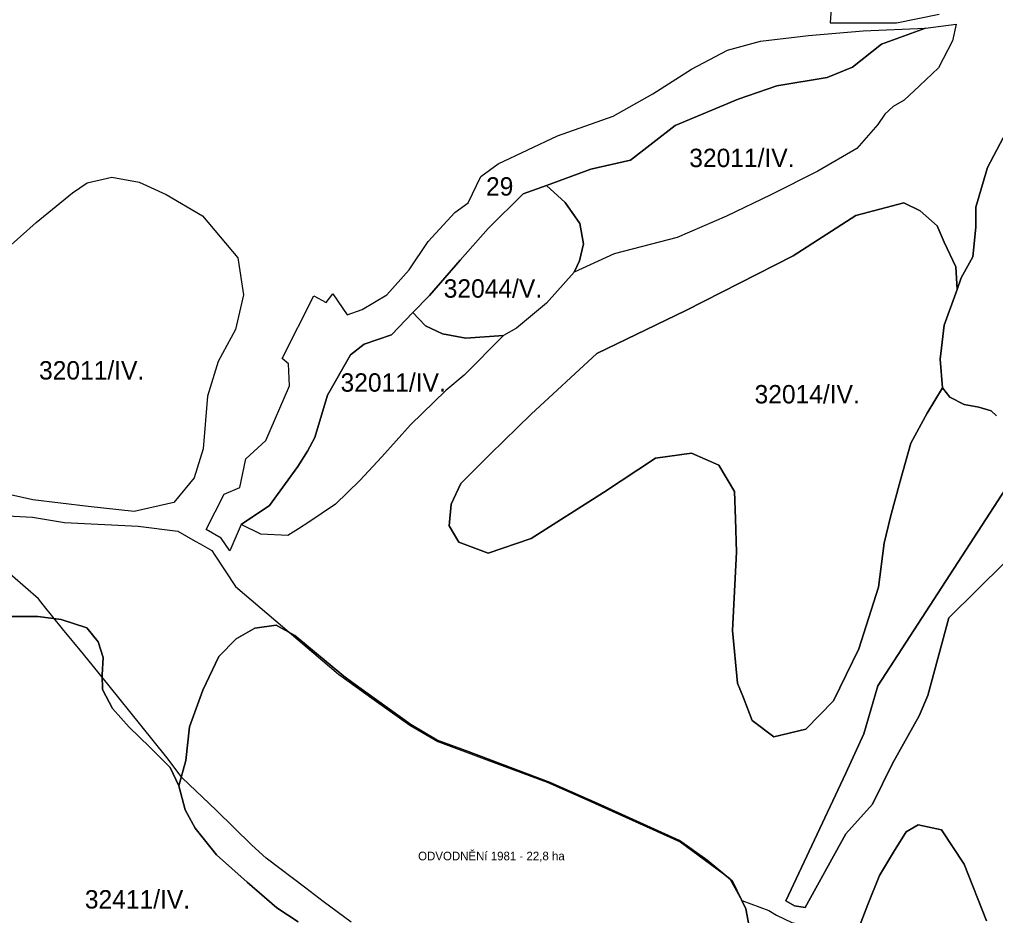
# Model space of a CAD drawing. Extents: x -521621 to -516761, y -1190184 to -1184927.
# Drawn here: x -518211 to -517414, y -1187665 to -1186934 of the extents above; entities that cross this region are included whole.
import ezdxf

# ---------------------------------------------------------------- set-up
doc = ezdxf.new("R2010")
doc.units = 0
doc.layers.add('BPEJ_s', color=7, linetype='Continuous')
doc.layers.add('odvodneni_s', color=7, linetype='Continuous')

msp = doc.modelspace()

# ---------------------------------------------------------------- linework, layer by layer
at = {"layer": 'BPEJ_s'}
for points in [[(-518029.72, -1187346.19), (-518038.98, -1187367.79), (-518045.96, -1187357.39), (-518058.12, -1187350.38), (-518043.45, -1187321.5), (-518030.79, -1187315.94), (-518025.93, -1187292.6), (-518009.65, -1187277.77), (-517990.31, -1187233), (-517991.03, -1187215.19), (-517996.11, -1187210.68), (-517970.35, -1187159.68), (-517960.2, -1187165.13), (-517954.93, -1187157.98), (-517943.27, -1187175.11), (-517931.05, -1187170.78), (-517910.74, -1187158.92), (-517892.69, -1187138.41), (-517877.03, -1187115.33), (-517855.2, -1187091.6), (-517844.41, -1187083.69), (-517834, -1187062.21), (-517819.95, -1187051.92), (-517771.39, -1187028.94), (-517726.14, -1187013.04), (-517693.57, -1186994.78), (-517662.24, -1186974.5), (-517632.81, -1186959.09), (-517605.84, -1186951.66), (-517566.49, -1186946.97), (-517521.9, -1186943.39), (-517470.99, -1186941.19), (-517445.99, -1186937.81), (-517449.03, -1186951.31), (-517460.58, -1186973.53), (-517476.03, -1186988.1), (-517488.46, -1186999.83), (-517497.52, -1187004.99), (-517504.38, -1187011.23), (-517509.98, -1187019.85), (-517527.2, -1187039.23), (-517559.06, -1187057.76), (-517597.31, -1187077.14), (-517633.59, -1187094.62), (-517673.9, -1187112.1), (-517725.3, -1187125.21), (-517757.89, -1187140.33), (-517780.4, -1187165.55), (-517804.92, -1187186.05), (-517815.67, -1187192.1), (-517847.58, -1187224.37), (-517862.7, -1187236.81), (-517891.59, -1187265.04), (-517914.77, -1187290.93), (-517932.91, -1187310.42), (-517952.73, -1187329.58), (-517974.57, -1187344.37), (-517982.97, -1187349.75), (-517991.7, -1187355.13), (-518013.54, -1187354.12)], [(-518029.72, -1187346.19), (-518038.98, -1187367.79), (-518045.96, -1187357.39), (-518058.12, -1187350.38), (-518043.45, -1187321.5), (-518030.79, -1187315.94), (-518025.93, -1187292.6), (-518009.65, -1187277.77), (-517990.31, -1187233), (-517991.03, -1187215.19), (-517996.11, -1187210.68), (-517970.35, -1187159.68), (-517960.2, -1187165.13), (-517954.93, -1187157.98), (-517943.27, -1187175.11), (-517931.05, -1187170.78), (-517910.74, -1187158.92), (-517892.69, -1187138.41), (-517877.03, -1187115.33), (-517855.2, -1187091.6), (-517844.41, -1187083.69), (-517834, -1187062.21), (-517819.95, -1187051.92), (-517771.39, -1187028.94), (-517726.14, -1187013.04), (-517693.57, -1186994.78), (-517662.24, -1186974.5), (-517632.81, -1186959.09), (-517605.84, -1186951.66), (-517566.49, -1186946.97), (-517521.9, -1186943.39), (-517470.99, -1186941.19), (-517507.04, -1186954.14), (-517530.71, -1186972.87), (-517551.35, -1186981.41), (-517592.36, -1186988.3), (-517624, -1186999.04), (-517675.47, -1187020.56), (-517711.98, -1187048.8), (-517744.18, -1187056.27), (-517780.4, -1187069.41), (-517799.61, -1187076.37), (-517828.16, -1187104.61), (-517851.06, -1187130.52), (-517875.94, -1187159.33), (-517889.51, -1187173.34), (-517906.94, -1187191.35), (-517929.34, -1187198.96), (-517940.34, -1187207.76), (-517959.14, -1187240.79), (-517969.54, -1187275.21), (-517975.54, -1187286.42), (-517983.54, -1187298.83), (-517995.59, -1187315.89), (-518006.5, -1187330.73)], [(-517780.4, -1187069.41), (-517744.18, -1187056.27), (-517711.98, -1187048.8), (-517675.47, -1187020.56), (-517624, -1186999.04), (-517592.36, -1186988.3), (-517551.35, -1186981.41), (-517530.71, -1186972.87), (-517507.04, -1186954.14), (-517470.99, -1186941.19), (-517445.99, -1186937.81), (-517449.03, -1186951.31), (-517460.58, -1186973.53), (-517476.03, -1186988.1), (-517488.46, -1186999.83), (-517497.52, -1187004.99), (-517504.38, -1187011.23), (-517509.98, -1187019.85), (-517527.2, -1187039.23), (-517559.06, -1187057.76), (-517597.31, -1187077.14), (-517633.59, -1187094.62), (-517673.9, -1187112.1), (-517725.3, -1187125.21), (-517757.89, -1187140.33), (-517753.52, -1187130.92), (-517750.16, -1187117.14), (-517753.18, -1187100.67), (-517765.28, -1187083.53)], [(-517889.51, -1187173.34), (-517875.94, -1187159.33), (-517851.06, -1187130.52), (-517828.16, -1187104.61), (-517799.61, -1187076.37), (-517780.4, -1187069.41), (-517765.28, -1187083.53), (-517753.18, -1187100.67), (-517750.16, -1187117.14), (-517753.52, -1187130.92), (-517757.89, -1187140.33), (-517780.4, -1187165.55), (-517804.92, -1187186.05), (-517815.67, -1187192.1), (-517846.24, -1187194.12), (-517865.39, -1187190.76), (-517879.16, -1187184.03), (-517884.54, -1187178.32)], [(-517457.21, -1187234.78), (-517469.69, -1187255.33), (-517483.07, -1187279.92), (-517491.81, -1187310.79), (-517499.72, -1187340.02), (-517504.83, -1187361.61), (-517509.62, -1187397.54), (-517525.58, -1187447.85), (-517546.33, -1187490.17), (-517568.67, -1187513.33), (-517595.01, -1187519.72), (-517612.56, -1187506.14), (-517619.74, -1187487.78), (-517624.53, -1187475.8), (-517628.52, -1187432.68), (-517625.33, -1187368.8), (-517626.13, -1187341.65), (-517626.93, -1187319.29), (-517639.7, -1187297.73), (-517662.04, -1187288.14), (-517691.57, -1187292.14), (-517733.86, -1187320.08), (-517792.92, -1187357.61), (-517828.03, -1187369.59), (-517851.97, -1187360.81), (-517859.95, -1187347.23), (-517858.36, -1187329.67), (-517850.38, -1187312.9), (-517826.44, -1187288.94), (-517792.92, -1187256.2), (-517739.45, -1187206.69), (-517666.83, -1187171.56), (-517579.04, -1187126.84), (-517527.97, -1187094.1), (-517488.87, -1187083.72), (-517475.57, -1187090.31), (-517461.64, -1187102.35), (-517455.94, -1187115.66), (-517446.44, -1187135.94), (-517445.18, -1187154.31), (-517455.94, -1187183.46), (-517459.11, -1187211.34)], [(-518029.72, -1187346.19), (-518006.5, -1187330.73), (-517995.59, -1187315.89), (-517983.54, -1187298.83), (-517975.54, -1187286.42), (-517969.54, -1187275.21), (-517959.14, -1187240.79), (-517940.34, -1187207.76), (-517929.34, -1187198.96), (-517906.94, -1187191.35), (-517889.51, -1187173.34), (-517884.54, -1187178.32), (-517879.16, -1187184.03), (-517865.39, -1187190.76), (-517846.24, -1187194.12), (-517815.67, -1187192.1), (-517847.58, -1187224.37), (-517862.7, -1187236.81), (-517891.59, -1187265.04), (-517914.77, -1187290.93), (-517932.91, -1187310.42), (-517952.73, -1187329.58), (-517974.57, -1187344.37), (-517982.97, -1187349.75), (-517991.7, -1187355.13), (-518013.54, -1187354.12)]]:
    msp.add_lwpolyline(points, close=True, dxfattribs=at)
for points in [[(-517407.81, -1187030.75), (-517420.48, -1187054.83), (-517429.98, -1187087.15), (-517429.98, -1187103.62), (-517432.51, -1187127.7), (-517442.01, -1187144.81), (-517445.18, -1187154.31), (-517446.44, -1187135.94), (-517455.94, -1187115.66), (-517461.64, -1187102.35), (-517475.57, -1187090.31), (-517488.87, -1187083.72), (-517527.97, -1187094.1), (-517579.04, -1187126.84), (-517666.83, -1187171.56), (-517739.45, -1187206.69), (-517792.92, -1187256.2), (-517826.44, -1187288.94), (-517850.38, -1187312.9), (-517858.36, -1187329.67), (-517859.95, -1187347.23), (-517851.97, -1187360.81), (-517828.03, -1187369.59), (-517792.92, -1187357.61), (-517733.86, -1187320.08), (-517691.57, -1187292.14), (-517662.04, -1187288.14), (-517639.7, -1187297.73), (-517626.93, -1187319.29), (-517626.13, -1187341.65), (-517625.33, -1187368.8), (-517628.52, -1187432.68), (-517624.53, -1187475.8), (-517619.74, -1187487.78), (-517612.56, -1187506.14), (-517595.01, -1187519.72), (-517568.67, -1187513.33), (-517546.33, -1187490.17), (-517525.58, -1187447.85), (-517509.62, -1187397.54), (-517504.83, -1187361.61), (-517499.72, -1187340.02), (-517491.81, -1187310.79), (-517483.07, -1187279.92), (-517469.69, -1187255.33), (-517457.21, -1187234.78), (-517451.13, -1187242.22), (-517439.66, -1187248.23), (-517427.65, -1187250.41), (-517417.55, -1187253.42), (-517413.18, -1187257.52)], [(-517413.18, -1187257.52), (-517417.55, -1187253.42), (-517427.65, -1187250.41), (-517439.66, -1187248.23), (-517451.13, -1187242.22), (-517457.21, -1187234.78), (-517459.11, -1187211.34), (-517455.94, -1187183.46), (-517445.18, -1187154.31), (-517442.01, -1187144.81), (-517432.51, -1187127.7), (-517429.98, -1187103.62), (-517429.98, -1187087.15), (-517420.48, -1187054.83), (-517407.81, -1187030.75)], [(-518222.49, -1187122.52), (-518196.96, -1187099.66), (-518167.39, -1187075.46), (-518155.3, -1187067.39), (-518135.14, -1187062.69), (-518112.97, -1187066.72), (-518090.8, -1187076.81), (-518061.24, -1187094.29), (-518032.35, -1187128.57), (-518027.65, -1187158.82), (-518034.36, -1187187.06), (-518048.47, -1187213.28), (-518057.21, -1187241.51), (-518060.57, -1187284.54), (-518067.96, -1187308.07), (-518084.75, -1187328.24), (-518117, -1187335.63), (-518154.63, -1187331.6), (-518199.64, -1187326.22), (-518235.25, -1187318.15)], [(-518222.49, -1187122.52), (-518196.96, -1187099.66), (-518167.39, -1187075.46), (-518155.3, -1187067.39), (-518135.14, -1187062.69), (-518112.97, -1187066.72), (-518090.8, -1187076.81), (-518061.24, -1187094.29), (-518032.35, -1187128.57), (-518027.65, -1187158.82), (-518034.36, -1187187.06), (-518048.47, -1187213.28), (-518057.21, -1187241.51), (-518060.57, -1187284.54), (-518067.96, -1187308.07), (-518084.75, -1187328.24), (-518117, -1187335.63), (-518154.63, -1187331.6), (-518199.64, -1187326.22), (-518235.25, -1187318.15)], [(-517383.4, -1187354.77), (-517451.95, -1187422.51), (-517469.3, -1187485.9), (-517476.24, -1187502.4), (-517497.93, -1187541.48), (-517514.42, -1187574.48), (-517536.11, -1187598.79), (-517569.29, -1187658.8), (-517578.06, -1187657.49), (-517585.17, -1187653.55), (-517536.11, -1187549.29), (-517521.36, -1187517.16), (-517510.08, -1187478.08), (-517399, -1187306.68)], [(-517399, -1187306.68), (-517510.08, -1187478.08), (-517521.36, -1187517.16), (-517536.11, -1187549.29), (-517585.17, -1187653.55), (-517578.06, -1187657.49), (-517569.29, -1187658.8), (-517536.11, -1187598.79), (-517514.42, -1187574.48), (-517497.93, -1187541.48), (-517476.24, -1187502.4), (-517469.3, -1187485.9), (-517451.95, -1187422.51), (-517383.4, -1187354.77)], [(-518219.49, -1187421.38), (-518195.69, -1187421.38), (-518176.51, -1187423.87), (-518155.55, -1187430.62), (-518146.31, -1187442), (-518142.41, -1187454.79), (-518143.12, -1187469.01), (-518142.76, -1187481.09), (-518134.59, -1187496.38), (-518121.09, -1187511.66), (-518104.4, -1187527.66), (-518087.7, -1187544.72), (-518080.6, -1187559.65), (-518075.27, -1187579.19), (-518067.1, -1187594.12), (-518049.7, -1187615.8), (-518024.83, -1187638.2), (-518000.68, -1187659.17), (-517983.27, -1187670.54)], [(-517612.9, -1187685.91), (-517617.66, -1187660.01), (-517628.56, -1187637.52), (-517649.24, -1187620.23), (-517671.84, -1187604.16), (-517736.22, -1187575.2), (-517777.6, -1187556.89), (-517845.83, -1187531.14), (-517869.6, -1187522.41), (-517891.18, -1187509.56), (-517938.45, -1187475.62), (-517945.94, -1187470), (-517985.88, -1187436.93), (-518001.03, -1187428.49), (-518018.44, -1187430.98), (-518033.71, -1187439.51), (-518047.92, -1187454.08), (-518061.06, -1187481.45), (-518071.72, -1187511.31), (-518074.92, -1187539.03), (-518080.6, -1187559.65), (-518087.7, -1187544.72), (-518104.4, -1187527.66), (-518121.09, -1187511.66), (-518134.59, -1187496.38), (-518142.76, -1187481.09), (-518143.12, -1187469.01), (-518142.41, -1187454.79), (-518146.31, -1187442), (-518155.55, -1187430.62), (-518176.51, -1187423.87), (-518195.69, -1187421.38), (-518219.49, -1187421.38)], [(-517983.27, -1187670.54), (-518000.68, -1187659.17), (-518024.83, -1187638.2), (-518049.7, -1187615.8), (-518067.1, -1187594.12), (-518075.27, -1187579.19), (-518080.6, -1187559.65), (-518074.92, -1187539.03), (-518071.72, -1187511.31), (-518061.06, -1187481.45), (-518047.92, -1187454.08), (-518033.71, -1187439.51), (-518018.44, -1187430.98), (-518001.03, -1187428.49), (-517985.88, -1187436.93), (-517945.94, -1187470), (-517938.45, -1187475.62), (-517891.18, -1187509.56), (-517869.6, -1187522.41), (-517845.83, -1187531.14), (-517777.6, -1187556.89), (-517736.22, -1187575.2), (-517671.84, -1187604.16), (-517649.24, -1187620.23), (-517628.56, -1187637.52), (-517617.66, -1187660.01), (-517612.9, -1187685.91)], [(-517540.69, -1187715.22), (-517518.21, -1187656.6), (-517508.68, -1187632.75), (-517497.2, -1187613.83), (-517486.81, -1187597.03), (-517477.21, -1187591.43), (-517458.02, -1187595.43), (-517439.63, -1187623.44), (-517421.23, -1187669.85)], [(-517421.23, -1187669.85), (-517439.63, -1187623.44), (-517458.02, -1187595.43), (-517477.21, -1187591.43), (-517486.81, -1187597.03), (-517497.2, -1187613.83), (-517508.68, -1187632.75), (-517518.21, -1187656.6), (-517540.69, -1187715.22)]]:
    msp.add_lwpolyline(points, dxfattribs=at)
at = {"layer": 'odvodneni_s'}
for points in [[(-517543.45, -1186858.01), (-517548.94, -1186936.72), (-517494.86, -1186936.67), (-517460.04, -1186929.71)], [(-518195.14, -1187407), (-518237.7, -1187369.82), (-518236.16, -1187338.27), (-518199.87, -1187340.38), (-518173.8, -1187344.62), (-518113.74, -1187347.57), (-518081.32, -1187351.71), (-518067.11, -1187359.78)], [(-518067.11, -1187359.78), (-518063.05, -1187362.09), (-518053.59, -1187367.46), (-518051.08, -1187371.3)], [(-518051.08, -1187371.3), (-518034.34, -1187396.85)], [(-518034.34, -1187396.85), (-517950.34, -1187468.33)], [(-518191.26, -1187411.98), (-518193.24, -1187409.43), (-518195.14, -1187407)], [(-518175.58, -1187431.48), (-518191.26, -1187411.98)], [(-518158.37, -1187452.16), (-518175.58, -1187431.48)], [(-518137.31, -1187477.94), (-518158.37, -1187452.16)], [(-517950.34, -1187468.33), (-517921.14, -1187489.42)], [(-518111.61, -1187510.19), (-518137.31, -1187477.94)], [(-517921.14, -1187489.42), (-517892.03, -1187510.14)], [(-518090.47, -1187536.35), (-518111.61, -1187510.19)], [(-517892.03, -1187510.14), (-517869.1, -1187523.41)], [(-517869.1, -1187523.41), (-517829.03, -1187538.42)], [(-518077.74, -1187553.09), (-518090.47, -1187536.35)], [(-517829.03, -1187538.42), (-517780.02, -1187556.66)], [(-518050.19, -1187579.33), (-518077.74, -1187553.09)], [(-517780.02, -1187556.66), (-517749.26, -1187570.2)], [(-517749.26, -1187570.2), (-517671.43, -1187605.2)], [(-518020.95, -1187608.03), (-518050.19, -1187579.33)], [(-518009.37, -1187618.6), (-518020.95, -1187608.03)], [(-517671.43, -1187605.2), (-517631.17, -1187634.96)], [(-517976.81, -1187643.14), (-518009.37, -1187618.6)], [(-517631.17, -1187634.96), (-517620.95, -1187653.19)], [(-517962.84, -1187653.94), (-517976.81, -1187643.14)], [(-517940, -1187670.92), (-517962.84, -1187653.94)], [(-517620.95, -1187653.19), (-517598.93, -1187661.48), (-517592.76, -1187665.26), (-517580.33, -1187671.15), (-517572.04, -1187673.09), (-517601.22, -1187736.39), (-517633.65, -1187806.72), (-517653.69, -1187806.18), (-517693.66, -1187793.99)]]:
    msp.add_lwpolyline(points, dxfattribs=at)

# ---------------------------------------------------------------- texts
at = {"layer": 'BPEJ_s'}
for s, p in [('32011/IV.', (-517663.93, -1187054.51)), ('29', (-517829.83, -1187077.78)), ('32044/V.', (-517864.36, -1187161.1)), ('32011/IV.', (-518194.66, -1187227.91)), ('32011/IV.', (-517948.56, -1187237.85)), ('32014/IV.', (-517610.63, -1187247.43)), ('32411/IV.', (-518157.25, -1187659.74))]:
    msp.add_text(s, height=15, dxfattribs=at).set_placement(p)
at = {"layer": 'odvodneni_s'}
msp.add_text('ODVODNĚNí 1981 - 22,8 ha', height=7, dxfattribs=at).set_placement((-517885.24, -1187620.39))

doc.saveas('drawing.dxf')
